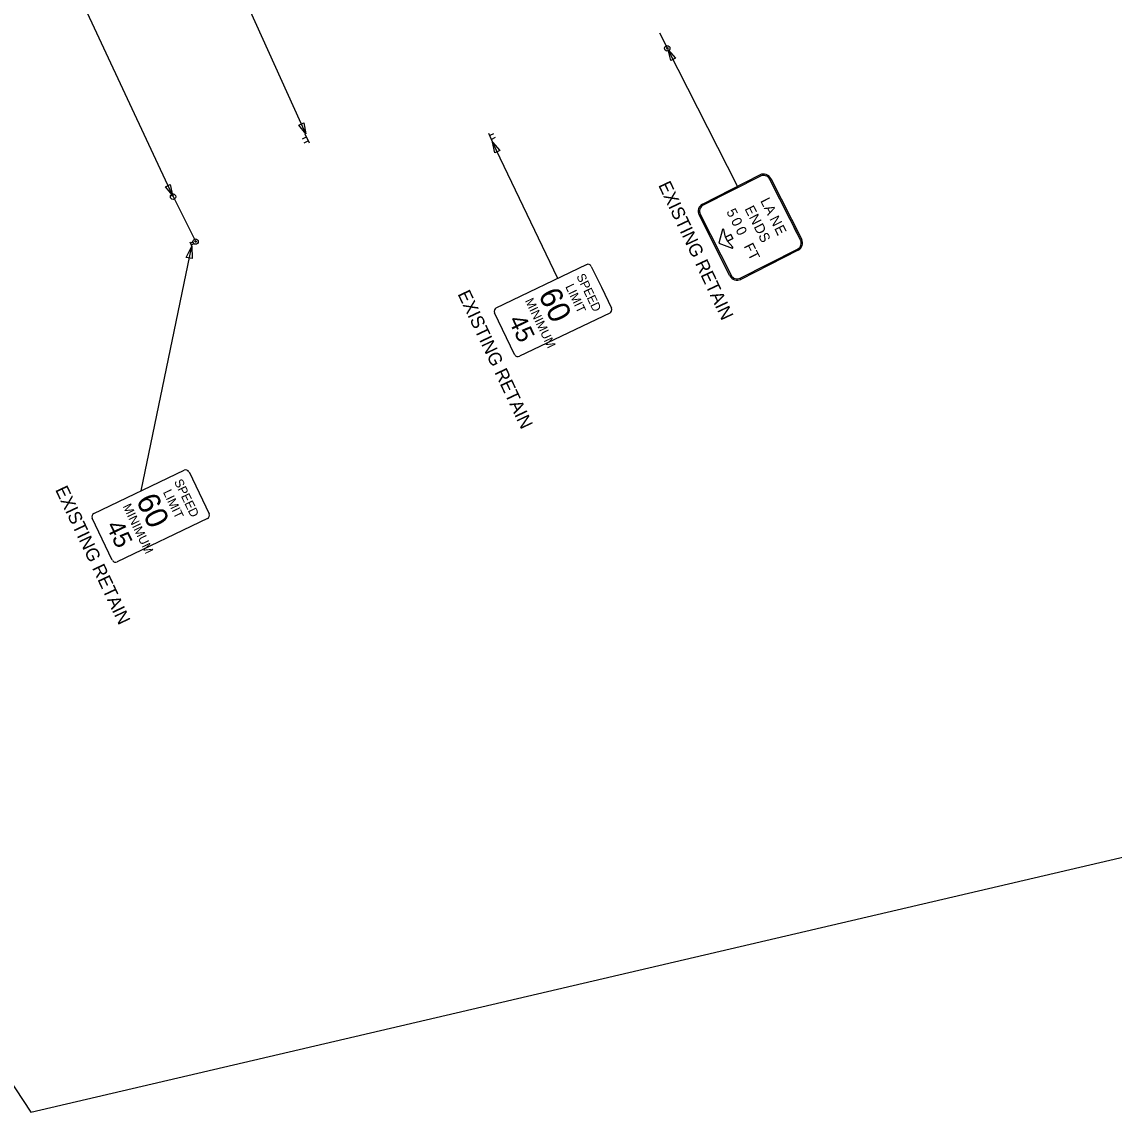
# Model space of a CAD drawing. Extents: x -5665 to 1997148, y 4 to 812485.
# Drawn here: x 1974648 to 1976903, y 802558 to 804808 of the extents above; entities that cross this region are included whole.
import ezdxf

# ---------------------------------------------------------------- set-up
doc = ezdxf.new("R2010")
doc.units = 0
for name, color, linetype in [('RD_EX_H20_TX', 7, 'Continuous'), ('RD_EX_Misc', 7, 'Continuous'), ('RD_PD_Final_TX', 7, 'Continuous'), ('RD_SHT_TX', 7, 'Continuous'), ('RD_Sketch10', 7, 'Continuous')]:
    doc.layers.add(name, color=color, linetype=linetype)

msp = doc.modelspace()

# ---------------------------------------------------------------- linework, layer by layer
at = {"layer": 'RD_EX_H20_TX'}
msp.add_lwpolyline([(1973692.8, 804229.2), (1974094.7, 803428), (1974666.8, 802557.5), (1980293.7, 803871.4), (1979319.1, 807956.8), (1972996.5, 806448.5), (1973203.6, 805580.6), (1973344.3, 805614.1)], close=True, dxfattribs=at)
at = {"layer": 'RD_PD_Final_TX'}
for points in [[(1975997.3, 804733.1), (1975987.5, 804728.1), (1975982.4, 804750.3)], [(1975220.1, 804594.6), (1975230.1, 804599.1), (1975234.2, 804576.8)], [(1975634.5, 804542.1), (1975624.6, 804537.4), (1975620, 804559.7)], [(1974944.7, 804467.4), (1974954.6, 804472.1), (1974959, 804449.8)], [(1974999.6, 804319.2), (1974987.5, 804321.8), (1974998.9, 804344.7)]]:
    msp.add_lwpolyline(points, close=True, dxfattribs=at)
at = {"layer": 'RD_SHT_TX'}
for p, q in [((1974959, 804449.8), (1974326.4, 805806.4)), ((1975234.2, 804576.8), (1975090.1, 804896.1)), ((1975964.1, 804785.3), (1975980.6, 804752.6)), ((1976125.5, 804468.6), (1975982.4, 804750.3)), ((1975242.1, 804557.2), (1975233.3, 804575.7)), ((1975611.2, 804578.2), (1975620, 804559.7)), ((1975622, 804576.9), (1975614, 804573.1)), ((1975227.8, 804566.5), (1975235.8, 804570.3)), ((1975231.3, 804558.4), (1975239.3, 804562.3)), ((1975625.5, 804568.9), (1975617.5, 804565)), ((1975754.8, 804278.4), (1975620, 804559.7)), ((1976053.2, 804431.8), (1976171.7, 804492)), ((1976173, 804489.6), (1976054.5, 804429.4)), ((1976173, 804489.6), (1976054.5, 804429.4)), ((1976171.7, 804492), (1976173, 804489.6)), ((1976171.7, 804492), (1976173, 804489.6)), ((1976171.7, 804492), (1976173, 804489.6)), ((1976171.7, 804492), (1976173, 804489.6)), ((1976173, 804489.6), (1976173, 804489.6)), ((1976173, 804489.6), (1976173, 804489.6)), ((1976191.6, 804483.5), (1976194, 804484.7)), ((1976191.6, 804483.5), (1976194, 804484.7)), ((1976191.6, 804483.5), (1976194, 804484.7)), ((1976191.6, 804483.5), (1976194, 804484.7)), ((1976194, 804484.7), (1976258, 804358.9)), ((1976255.5, 804357.6), (1976191.6, 804483.5)), ((1976255.5, 804357.6), (1976191.6, 804483.5)), ((1974959, 804449.8), (1975007.1, 804353.7)), ((1976054.5, 804429.4), (1976053.2, 804431.8)), ((1976054.5, 804429.4), (1976053.2, 804431.8)), ((1976054.5, 804429.4), (1976053.2, 804431.8)), ((1976054.5, 804429.4), (1976053.2, 804431.8)), ((1976046, 804409.5), (1976048.4, 804410.8)), ((1976046, 804409.5), (1976048.4, 804410.8)), ((1976046, 804409.5), (1976048.4, 804410.8)), ((1976046, 804409.5), (1976048.4, 804410.8)), ((1976109.9, 804283.6), (1976046, 804409.5)), ((1976048.4, 804410.8), (1976112.4, 804284.9)), ((1976048.4, 804410.8), (1976112.4, 804284.9)), ((1976048.4, 804410.8), (1976048.4, 804410.8)), ((1976048.4, 804410.8), (1976048.4, 804410.8)), ((1976094.5, 804379.3), (1976086.7, 804351)), ((1976094.5, 804379.3), (1976086.7, 804351)), ((1976094.5, 804379.3), (1976095.8, 804379)), ((1976095.8, 804379), (1976094.5, 804379.3)), ((1976095.8, 804379), (1976094.5, 804379.3)), ((1976095.8, 804379), (1976094.5, 804379.3)), ((1976095.8, 804379), (1976097.2, 804379.3)), ((1976095.8, 804379), (1976097.2, 804379.3)), ((1976097.2, 804379.3), (1976095.8, 804379)), ((1976097.2, 804379.3), (1976095.8, 804379)), ((1976100.7, 804363.2), (1976097.2, 804379.3)), ((1976100.7, 804363.2), (1976097.2, 804379.3)), ((1976255.5, 804357.6), (1976242.7, 804382.8)), ((1976255.5, 804357.6), (1976242.7, 804382.8)), ((1974994.8, 804353.5), (1974999.2, 804344.2)), ((1975000.2, 804352.8), (1974996.2, 804350.9)), ((1976086.7, 804351), (1976114.2, 804340.6)), ((1976086.7, 804351), (1976114.2, 804340.6)), ((1976100.7, 804363.2), (1976111.8, 804368.8)), ((1976111.8, 804368.8), (1976100.7, 804363.2)), ((1976104.8, 804355.2), (1976100.7, 804363.2)), ((1976104.8, 804355.2), (1976100.7, 804363.2)), ((1976104.8, 804355.2), (1976100.7, 804363.2)), ((1976100.7, 804363.2), (1976104.8, 804355.2)), ((1976115.9, 804360.8), (1976104.8, 804355.2)), ((1976104.8, 804355.2), (1976115.9, 804360.8)), ((1976115.7, 804342.9), (1976104.8, 804355.2)), ((1976115.7, 804342.9), (1976104.8, 804355.2)), ((1976111.8, 804368.8), (1976115.9, 804360.8)), ((1976111.8, 804368.8), (1976111.8, 804368.8)), ((1976115.9, 804360.8), (1976111.8, 804368.8)), ((1976207.5, 804368.6), (1976209, 804369.4)), ((1976258, 804358.9), (1976255.5, 804357.6)), ((1976258, 804358.9), (1976255.5, 804357.6)), ((1976258, 804358.9), (1976255.5, 804357.6)), ((1976258, 804358.9), (1976255.5, 804357.6)), ((1976256, 804357.9), (1976255.5, 804357.6)), ((1976256, 804357.9), (1976255.5, 804357.6)), ((1976256, 804357.9), (1976255.5, 804357.6)), ((1976256, 804357.9), (1976255.5, 804357.6)), ((1976255.5, 804357.6), (1976255.5, 804357.6)), ((1976255.5, 804357.6), (1976255.5, 804357.6)), ((1976255.5, 804357.6), (1976255.5, 804357.6)), ((1976255.5, 804357.6), (1976255.5, 804357.6)), ((1974894.5, 803839.6), (1974998.9, 804344.7)), ((1975001.9, 804348.8), (1974997.9, 804346.9)), ((1976114.6, 804341.9), (1976114.2, 804340.6)), ((1976114.6, 804341.9), (1976114.2, 804340.6)), ((1976114.2, 804340.6), (1976114.6, 804341.9)), ((1976114.2, 804340.6), (1976114.6, 804341.9)), ((1976114.2, 804340.6), (1976114.2, 804340.6)), ((1976115.7, 804342.9), (1976114.6, 804341.9)), ((1976114.6, 804341.9), (1976115.7, 804342.9)), ((1976114.6, 804341.9), (1976115.7, 804342.9)), ((1976114.6, 804341.9), (1976115.7, 804342.9)), ((1976131, 804278.8), (1976249.4, 804339)), ((1976131, 804278.8), (1976249.4, 804339)), ((1976250.7, 804336.5), (1976132.2, 804276.4)), ((1976249.4, 804339), (1976250.7, 804336.5)), ((1976249.4, 804339), (1976250.7, 804336.5)), ((1976249.4, 804339), (1976250.7, 804336.5)), ((1976249.4, 804339), (1976250.7, 804336.5)), ((1975627.4, 804217.4), (1975813.8, 804306.7)), ((1975823.7, 804303.2), (1975844.4, 804260)), ((1976112.4, 804284.9), (1976109.9, 804283.6)), ((1976112.4, 804284.9), (1976109.9, 804283.6)), ((1976112.4, 804284.9), (1976109.9, 804283.6)), ((1976112.4, 804284.9), (1976109.9, 804283.6)), ((1975844.4, 804260), (1975865.1, 804216.7)), ((1976132.2, 804276.4), (1976131, 804278.8)), ((1976132.2, 804276.4), (1976131, 804278.8)), ((1976131, 804278.8), (1976131, 804278.8)), ((1976132.2, 804276.4), (1976131, 804278.8)), ((1976132.2, 804276.4), (1976131, 804278.8)), ((1976131, 804278.8), (1976131, 804278.8)), ((1975665.4, 804121), (1975624, 804207.5)), ((1975861.7, 804206.8), (1975675.3, 804117.5)), ((1974797, 803793.1), (1974983.4, 803882.5)), ((1974993.3, 803879), (1975014, 803835.7)), ((1975014, 803835.7), (1975034.8, 803792.4)), ((1974835, 803696.8), (1974793.6, 803783.3)), ((1975031.3, 803782.6), (1974844.9, 803693.3))]:
    msp.add_line(p, q, dxfattribs=at)
for centre in [(1975980.3, 804753.2), (1974960.3, 804447), (1975006.9, 804354.3)]:
    msp.add_circle(centre, 5.54, dxfattribs=at)
for centre, radius, start, end in [((1976179.2, 804477.2), 16.6, 26.9261, 116.9261), ((1976179.2, 804477.2), 16.6, 26.9261, 116.9261), ((1976179.2, 804477.2), 13.8, 26.9261, 116.9261), ((1976179.2, 804477.2), 13.8, 26.9261, 116.9261), ((1976060.8, 804417), 16.6, 116.9261, 206.9261), ((1976060.8, 804417), 16.6, 116.9261, 206.9261), ((1976060.8, 804417), 13.8, 116.9261, 206.9261), ((1976060.8, 804417), 13.8, 116.9261, 206.9261), ((1976095.8, 804379), 1.38, 12.4534, 163.901), ((1976095.8, 804379), 1.38, 12.4534, 163.901), ((1976243.2, 804351.3), 13.8, 296.9261, 26.9261), ((1976243.2, 804351.3), 13.8, 296.9261, 26.9261), ((1976243.2, 804351.3), 16.6, 296.9261, 26.9261), ((1976243.2, 804351.3), 16.6, 296.9261, 26.9261), ((1976114.6, 804341.9), 1.38, 249.9512, 41.3987), ((1976114.6, 804341.9), 1.38, 249.9512, 41.3987), ((1976114.6, 804341.9), 1.38, 249.9511577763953, 249.95115983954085), ((1975817, 804300), 7.38, 25.6005, 115.6005), ((1976124.7, 804291.2), 16.6, 206.9261, 296.9261), ((1976124.7, 804291.2), 16.6, 206.9261, 296.9261), ((1976124.7, 804291.2), 13.8, 206.9261, 296.9261), ((1976124.7, 804291.2), 13.8, 206.9261, 296.9261), ((1975630.6, 804210.7), 7.38, 115.6005, 205.6005), ((1975858.5, 804213.5), 7.38, 295.6005, 25.6005), ((1975672.1, 804124.2), 7.38, 205.6005, 295.6005), ((1974986.6, 803875.8), 7.38, 25.6005, 115.6005), ((1974800.2, 803786.5), 7.38, 115.6005, 205.6005), ((1975028.1, 803789.3), 7.38, 295.6005, 25.6005), ((1974841.7, 803699.9), 7.38, 205.6005, 295.6005)]:
    msp.add_arc(centre, radius, start, end, dxfattribs=at)
at = {"layer": 'RD_Sketch10'}
for centre in [(1975980.3, 804753.2), (1974959, 804449.8), (1975006.9, 804354.3)]:
    msp.add_circle(centre, 1.5, dxfattribs=at)

# ---------------------------------------------------------------- texts
at = {"layer": 'RD_EX_Misc'}
for p in [(1975961.3, 804471), (1975547.2, 804246.3), (1974716.6, 803842.4)]:
    msp.add_text('EXISTING RETAIN', height=27, rotation=295.2122, dxfattribs=at).set_placement(p)
at = {"layer": 'RD_SHT_TX'}
for s, height, rotation, p in [('L', 20.8, 296.9261, (1976171.9, 804438.5)), ('5', 20.8, 296.9261, (1976101.8, 804416.1)), ('E', 20.8, 296.9261, (1976139.5, 804422.1)), ('A', 20.8, 296.9261, (1976179.5, 804423.7)), ('0', 20.8, 296.9261, (1976111.3, 804397.4)), ('N', 20.8, 296.9261, (1976148.4, 804404.6)), ('N', 20.8, 296.9261, (1976190.8, 804401.3)), ('0', 20.8, 296.9261, (1976120.8, 804378.6)), ('D', 20.8, 296.9261, (1976158.3, 804385.1)), ('S', 20.8, 296.9261, (1976167.7, 804366.6)), ('E', 20.8, 296.9261, (1976200.7, 804381.8)), ('F', 20.8, 296.9261, (1976138, 804344.8)), ('T', 20.8, 296.9261, (1976146.2, 804328.6)), ('SPEED', 18.45, 295.6005, (1975792.4, 804283)), ('LIMIT', 18.45, 295.6005, (1975769.5, 804261.5)), ('MINIMUM', 18.45, 295.6005, (1975686.3, 804232.3)), ('60', 46.14, 295.6005, (1975713.5, 804245)), ('45', 36.91, 295.6005, (1975651.7, 804192.3)), ('SPEED', 18.45, 295.6005, (1974962, 803858.8)), ('60', 46.14, 295.6005, (1974883.1, 803820.7)), ('LIMIT', 18.45, 295.6005, (1974939.1, 803837.3)), ('MINIMUM', 18.45, 295.6005, (1974855.9, 803808)), ('45', 36.91, 295.6005, (1974821.3, 803768.1))]:
    msp.add_text(s, height=height, rotation=rotation, dxfattribs=at).set_placement(p)

doc.saveas('drawing.dxf')
